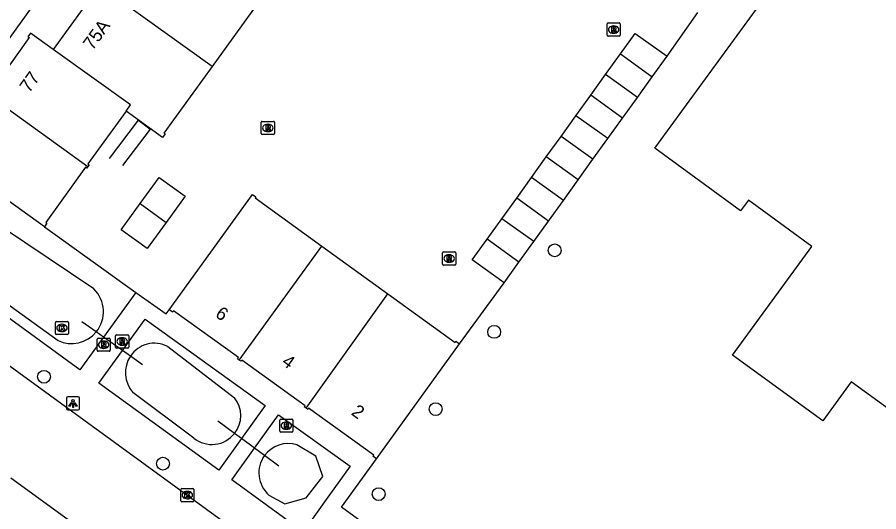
# Model space of a CAD drawing. Extents: x 159675 to 160530, y 382179 to 382901.
# Drawn here: x 160034.9 to 160100.6, y 382438.2 to 382475.9 of the extents above; entities that cross this region are included whole.
import ezdxf

# ---------------------------------------------------------------- set-up
doc = ezdxf.new("R2010")
doc.units = 0
for name, color, linetype in [('IMGEO_Boom', 7, 'Continuous'), ('IMGEO_Duiker', 7, 'Continuous'), ('IMGEO_Erf', 7, 'Continuous'), ('IMGEO_Groenvoorziening', 7, 'Continuous'), ('IMGEO_Hek', 7, 'Continuous'), ('IMGEO_Kolk', 7, 'Continuous'), ('IMGEO_Lichtpunt', 7, 'Continuous'), ('IMGEO_Pand', 7, 'Continuous'), ('IMGEO_Pand_nummerreeks', 7, 'Continuous'), ('IMGEO_Rijbaan_lokaal_open', 7, 'Continuous'), ('IMGEO_Rioolput', 7, 'Continuous'), ('IMGEO_Voetpad_open', 7, 'Continuous'), ('IMGEO_Waterloop', 7, 'Continuous')]:
    doc.layers.add(name, color=color, linetype=linetype)

msp = doc.modelspace()

# ---------------------------------------------------------------- linework, layer by layer
at = {"layer": 'IMGEO_Boom'}
for centre in [(160075.863, 382458.124), (160071.249, 382451.914), (160036.941, 382448.488), (160066.793, 382446.022), (160046.006, 382441.864), (160062.444, 382439.547)]:
    msp.add_circle(centre, 0.489, dxfattribs=at)
at = {"layer": 'IMGEO_Duiker'}
for points in [[(160044.452, 382449.408), (160043.529, 382450.059), (160042.922, 382450.487), (160041.474, 382451.508), (160040.915, 382451.903), (160039.813, 382452.68)], [(160054.834, 382441.676), (160053.747, 382442.479), (160052.977, 382443.048), (160051.982, 382443.784), (160051.461, 382444.169), (160050.195, 382445.105)]]:
    msp.add_lwpolyline(points, dxfattribs=at)
at = {"layer": 'IMGEO_Erf'}
for points in [[(160084.42, 382472.917), (160086.78, 382476.254)], [(160068.6, 382451.01), (160072.007, 382455.649)]]:
    msp.add_lwpolyline(points, dxfattribs=at)
at = {"layer": 'IMGEO_Groenvoorziening'}
msp.add_lwpolyline([(160036.972, 382459.928), (160043.937, 382454.91)], dxfattribs=at)
at = {"layer": 'IMGEO_Hek'}
msp.add_lwpolyline([(160041.939, 382465.12), (160044.148, 382468.038), (160045.027, 382467.372), (160042.916, 382464.583)], dxfattribs=at)
at = {"layer": 'IMGEO_Kolk'}
for p, q in [((160037.807, 382451.784), (160037.807, 382452.636)), ((160037.882, 382452.71), (160038.734, 382452.71)), ((160038.808, 382452.636), (160038.808, 382451.784)), ((160038.318, 382451.93), (160038.293, 382451.93)), ((160038.295, 382452.49), (160038.32, 382452.49)), ((160038.734, 382451.71), (160037.882, 382451.71)), ((160047.363, 382439.043), (160047.363, 382439.895)), ((160047.438, 382439.969), (160048.29, 382439.969)), ((160047.851, 382439.749), (160047.876, 382439.749)), ((160048.364, 382439.895), (160048.364, 382439.043)), ((160048.29, 382438.969), (160047.438, 382438.969)), ((160047.874, 382439.189), (160047.849, 382439.189))]:
    msp.add_line(p, q, dxfattribs=at)
for points in [[(160037.807, 382451.784), (160037.807, 382452.636)], [(160037.882, 382452.71), (160038.734, 382452.71)], [(160038.808, 382452.636), (160038.808, 382451.784)], [(160038.128, 382452.41), (160038.251, 382452.41), (160038.251, 382452.259), (160038.381, 382452.41), (160038.545, 382452.41), (160038.399, 382452.259), (160038.552, 382452.01), (160038.4, 382452.01), (160038.315, 382452.174), (160038.251, 382452.107), (160038.251, 382452.01), (160038.128, 382452.01), (160038.128, 382452.41)], [(160038.734, 382451.71), (160037.882, 382451.71)], [(160047.363, 382439.043), (160047.363, 382439.895)], [(160047.438, 382439.969), (160048.29, 382439.969)], [(160047.684, 382439.669), (160047.807, 382439.669), (160047.807, 382439.518), (160047.937, 382439.669), (160048.101, 382439.669), (160047.955, 382439.518), (160048.108, 382439.269), (160047.956, 382439.269), (160047.871, 382439.433), (160047.807, 382439.366), (160047.807, 382439.269), (160047.684, 382439.269), (160047.684, 382439.669)], [(160048.364, 382439.895), (160048.364, 382439.043)], [(160048.29, 382438.969), (160047.438, 382438.969)]]:
    msp.add_lwpolyline(points, dxfattribs=at)
for centre, start, end in [((160037.884, 382452.634), 91.55205, 178.44795), ((160037.884, 382452.634), 91.55205, 178.44795), ((160038.732, 382452.634), 1.55205, 88.44795), ((160038.732, 382452.634), 1.55205, 88.44795), ((160037.884, 382451.786), 181.55205, 268.44795), ((160037.884, 382451.786), 181.55205, 268.44795), ((160038.732, 382451.786), 271.55205, 358.44795), ((160038.732, 382451.786), 271.55205, 358.44795), ((160047.44, 382439.893), 91.55205, 178.44795), ((160047.44, 382439.893), 91.55205, 178.44795), ((160048.288, 382439.893), 1.55205, 88.44795), ((160048.288, 382439.893), 1.55205, 88.44795), ((160047.44, 382439.045), 181.55205, 268.44795), ((160047.44, 382439.045), 181.55205, 268.44795), ((160048.288, 382439.045), 271.55205, 358.44795), ((160048.288, 382439.045), 271.55205, 358.44795)]:
    msp.add_arc(centre, 0.0765, start, end, dxfattribs=at)
for centre, major_axis, ratio, start_param, end_param in [((160038.294, 382452.21), (-0.387, 0.002), 0.722429, 4.712389, 7.853982), ((160038.319, 382452.21), (-0.39, 0.002), 0.717154, 1.570796, 4.712389), ((160047.85, 382439.469), (-0.387, 0.002), 0.722429, 4.712389, 7.853982), ((160047.875, 382439.469), (-0.39, 0.002), 0.717154, 1.570796, 4.712389)]:
    msp.add_ellipse(centre, major_axis=major_axis, ratio=ratio, start_param=start_param, end_param=end_param, dxfattribs=at)
at = {"layer": 'IMGEO_Lichtpunt'}
for p, q in [((160038.654, 382446.861), (160038.654, 382446.054)), ((160038.654, 382446.861), (160038.654, 382446.054)), ((160039.556, 382446.956), (160038.748, 382446.956)), ((160039.556, 382446.956), (160038.748, 382446.956)), ((160039.65, 382446.054), (160039.65, 382446.861)), ((160039.65, 382446.054), (160039.65, 382446.861)), ((160038.748, 382445.96), (160039.556, 382445.96)), ((160038.748, 382445.96), (160039.556, 382445.96))]:
    msp.add_line(p, q, dxfattribs=at)
for points in [[(160039.028, 382446.525), (160039.067, 382446.497), (160038.879, 382446.235), (160038.841, 382446.262), (160039.028, 382446.525)], [(160039.13, 382446.477), (160039.177, 382446.477), (160039.177, 382446.155), (160039.13, 382446.155), (160039.13, 382446.477)], [(160039.24, 382446.497), (160039.278, 382446.524), (160039.465, 382446.262), (160039.426, 382446.234), (160039.24, 382446.497)]]:
    msp.add_lwpolyline(points, dxfattribs=at)
msp.add_circle((160039.153, 382446.659), 0.0994, dxfattribs=at)
for centre, start, end in [((160038.748, 382446.861), 90, 180), ((160038.748, 382446.861), 90, 180), ((160039.556, 382446.861), 0, 90), ((160039.556, 382446.861), 0, 90), ((160038.748, 382446.054), 180, 270), ((160038.748, 382446.054), 180, 270), ((160039.556, 382446.054), 270, 0), ((160039.556, 382446.054), 270, 360)]:
    msp.add_arc(centre, 0.0946, start, end, dxfattribs=at)
at = {"layer": 'IMGEO_Pand'}
for points in [[(160096.303, 382445.131), (160089.403, 382450.139), (160095.446, 382458.418), (160090.622, 382461.94), (160090.027, 382461.125), (160083.485, 382465.902), (160096.525, 382483.765), (160111.322, 382472.965)], [(160041.08, 382478.387), (160040.985, 382478.255), (160041.074, 382478.191), (160037.64, 382473.43)], [(160049.748, 382472.149), (160041.08, 382478.387)], [(160053.437, 382477.262), (160049.748, 382472.149)], [(160037.64, 382473.43), (160035.91, 382474.671), (160035.721, 382474.409), (160035.811, 382474.345), (160032.781, 382470.131), (160032.692, 382470.195), (160032.597, 382470.065)], [(160080.864, 382473.092), (160081.992, 382474.662), (160084.42, 382472.917)], [(160043.198, 382468.743), (160043.531, 382469.204), (160037.64, 382473.43)], [(160079.735, 382471.523), (160080.864, 382473.092)], [(160080.864, 382473.092), (160083.291, 382471.347)], [(160083.291, 382471.347), (160084.42, 382472.917)], [(160049.748, 382472.149), (160046.079, 382467.062), (160046.168, 382466.997), (160045.981, 382466.738), (160043.198, 382468.743)], [(160078.607, 382469.953), (160079.735, 382471.523)], [(160082.163, 382469.777), (160079.735, 382471.523)], [(160082.163, 382469.777), (160083.291, 382471.347)], [(160032.597, 382470.065), (160040.276, 382464.504)], [(160077.478, 382468.383), (160078.607, 382469.953)], [(160081.035, 382468.207), (160078.607, 382469.953)], [(160081.035, 382468.207), (160082.163, 382469.777)], [(160043.198, 382468.743), (160040.291, 382464.715), (160040.381, 382464.65), (160040.276, 382464.504)], [(160076.35, 382466.813), (160077.478, 382468.383)], [(160079.906, 382466.638), (160077.478, 382468.383)], [(160079.906, 382466.638), (160081.035, 382468.207)], [(160075.221, 382465.244), (160076.35, 382466.813)], [(160078.778, 382465.068), (160076.35, 382466.813)], [(160078.778, 382465.068), (160079.906, 382466.638)], [(160036.972, 382459.928), (160029.413, 382465.356)], [(160074.093, 382463.674), (160075.221, 382465.244)], [(160077.649, 382463.498), (160075.221, 382465.244)], [(160077.649, 382463.498), (160078.778, 382465.068)], [(160040.276, 382464.504), (160040.193, 382464.389), (160040.103, 382464.454), (160037.071, 382460.254), (160037.16, 382460.189), (160036.972, 382459.928)], [(160044.28, 382461.69), (160045.728, 382463.69), (160047.704, 382462.258), (160046.256, 382460.258)], [(160072.964, 382462.104), (160074.093, 382463.674)], [(160076.521, 382461.928), (160074.093, 382463.674)], [(160076.521, 382461.928), (160077.649, 382463.498)], [(160046.492, 382453.604), (160052.826, 382462.394), (160053.085, 382462.205), (160053.022, 382462.117), (160058.111, 382458.444)], [(160071.836, 382460.534), (160072.964, 382462.104)], [(160075.392, 382460.359), (160072.964, 382462.104)], [(160075.392, 382460.359), (160076.521, 382461.928)], [(160046.256, 382460.258), (160044.807, 382458.257), (160042.831, 382459.689), (160044.28, 382461.69)], [(160044.28, 382461.69), (160046.256, 382460.258)], [(160070.707, 382458.965), (160071.836, 382460.534)], [(160074.264, 382458.789), (160071.836, 382460.534)], [(160074.264, 382458.789), (160075.392, 382460.359)], [(160072.007, 382455.649), (160069.579, 382457.395), (160070.707, 382458.965)], [(160073.136, 382457.219), (160070.707, 382458.965)], [(160073.136, 382457.219), (160074.264, 382458.789)], [(160051.825, 382449.763), (160058.111, 382458.444)], [(160058.111, 382458.444), (160063.155, 382454.804)], [(160072.007, 382455.649), (160073.136, 382457.219)], [(160056.909, 382446.1), (160063.155, 382454.804)], [(160063.155, 382454.804), (160068.274, 382451.11), (160068.338, 382451.199), (160068.6, 382451.01)], [(160051.825, 382449.763), (160051.694, 382449.857), (160051.758, 382449.946), (160046.818, 382453.504), (160046.754, 382453.415), (160046.492, 382453.604)], [(160062.271, 382442.237), (160068.6, 382451.01)], [(160056.909, 382446.1), (160056.778, 382446.194), (160056.843, 382446.284), (160052.02, 382449.758), (160051.955, 382449.668), (160051.825, 382449.763)], [(160099.082, 382425.521), (160110.426, 382441.152), (160107.233, 382443.47), (160106.406, 382442.33), (160098.456, 382448.099), (160096.303, 382445.131)], [(160062.271, 382442.237), (160062.009, 382442.426), (160062.074, 382442.515), (160057.105, 382446.095), (160057.04, 382446.006), (160056.909, 382446.1)]]:
    msp.add_lwpolyline(points, dxfattribs=at)
at = {"layer": 'IMGEO_Rijbaan_lokaal_open'}
for points in [[(160018.366, 382460.946), (160123.455, 382384.426)], [(160099.29, 382393.592), (160034.415, 382440.769)]]:
    msp.add_lwpolyline(points, dxfattribs=at)
at = {"layer": 'IMGEO_Rioolput'}
for p, q in [((160079.858, 382474.527), (160079.858, 382475.379)), ((160079.933, 382475.453), (160080.785, 382475.453)), ((160080.346, 382475.233), (160080.371, 382475.233)), ((160080.859, 382475.379), (160080.859, 382474.527)), ((160080.785, 382474.453), (160079.933, 382474.453)), ((160080.369, 382474.673), (160080.344, 382474.673)), ((160053.503, 382467.031), (160053.503, 382467.883)), ((160053.578, 382467.957), (160054.43, 382467.957)), ((160053.991, 382467.737), (160054.016, 382467.737)), ((160054.504, 382467.883), (160054.504, 382467.031)), ((160054.014, 382467.177), (160053.989, 382467.177)), ((160054.43, 382466.957), (160053.578, 382466.957)), ((160067.315, 382457.078), (160067.315, 382457.93)), ((160067.39, 382458.004), (160068.242, 382458.004)), ((160068.316, 382457.93), (160068.316, 382457.078)), ((160067.826, 382457.224), (160067.801, 382457.224)), ((160067.803, 382457.784), (160067.828, 382457.784)), ((160068.242, 382457.004), (160067.39, 382457.004)), ((160040.988, 382450.506), (160040.988, 382451.358)), ((160041.063, 382451.432), (160041.915, 382451.432)), ((160041.989, 382451.358), (160041.989, 382450.506)), ((160042.394, 382450.753), (160042.394, 382451.605)), ((160042.469, 382451.679), (160043.321, 382451.679)), ((160042.882, 382451.459), (160042.907, 382451.459)), ((160043.395, 382451.605), (160043.395, 382450.753)), ((160041.499, 382450.652), (160041.474, 382450.652)), ((160041.476, 382451.212), (160041.501, 382451.212)), ((160043.321, 382450.679), (160042.469, 382450.679)), ((160042.905, 382450.899), (160042.88, 382450.899)), ((160041.915, 382450.432), (160041.063, 382450.432)), ((160054.913, 382444.341), (160054.913, 382445.193)), ((160054.988, 382445.267), (160055.84, 382445.267)), ((160055.401, 382445.047), (160055.426, 382445.047)), ((160055.914, 382445.193), (160055.914, 382444.341)), ((160055.84, 382444.267), (160054.988, 382444.267)), ((160055.424, 382444.487), (160055.399, 382444.487))]:
    msp.add_line(p, q, dxfattribs=at)
for points in [[(160079.858, 382474.527), (160079.858, 382475.379)], [(160079.933, 382475.453), (160080.785, 382475.453)], [(160080.447, 382475.151), (160080.195, 382475.153), (160080.195, 382474.753)], [(160080.195, 382474.753), (160080.319, 382474.753), (160080.319, 382474.915), (160080.33, 382474.915)], [(160080.373, 382475.072), (160080.319, 382475.072), (160080.319, 382474.991)], [(160080.319, 382474.991), (160080.371, 382474.991)], [(160080.859, 382475.379), (160080.859, 382474.527)], [(160080.785, 382474.453), (160079.933, 382474.453)], [(160080.377, 382474.886), (160080.448, 382474.753), (160080.588, 382474.753), (160080.523, 382474.879)], [(160053.503, 382467.031), (160053.503, 382467.883)], [(160053.578, 382467.957), (160054.43, 382467.957)], [(160054.504, 382467.883), (160054.504, 382467.031)], [(160054.092, 382467.655), (160053.84, 382467.657), (160053.84, 382467.257)], [(160053.84, 382467.257), (160053.964, 382467.257), (160053.964, 382467.419), (160053.975, 382467.419)], [(160054.018, 382467.576), (160053.964, 382467.576), (160053.964, 382467.495)], [(160053.964, 382467.495), (160054.016, 382467.495)], [(160054.022, 382467.39), (160054.093, 382467.257), (160054.233, 382467.257), (160054.168, 382467.383)], [(160054.43, 382466.957), (160053.578, 382466.957)], [(160067.315, 382457.078), (160067.315, 382457.93)], [(160067.39, 382458.004), (160068.242, 382458.004)], [(160068.316, 382457.93), (160068.316, 382457.078)], [(160067.904, 382457.702), (160067.652, 382457.704), (160067.652, 382457.304)], [(160067.652, 382457.304), (160067.776, 382457.304), (160067.776, 382457.466), (160067.787, 382457.466)], [(160067.83, 382457.623), (160067.776, 382457.623), (160067.776, 382457.542)], [(160067.776, 382457.542), (160067.828, 382457.542)], [(160067.834, 382457.437), (160067.905, 382457.304), (160068.045, 382457.304), (160067.98, 382457.43)], [(160068.242, 382457.004), (160067.39, 382457.004)], [(160040.988, 382450.506), (160040.988, 382451.358)], [(160041.063, 382451.432), (160041.915, 382451.432)], [(160041.989, 382451.358), (160041.989, 382450.506)], [(160042.394, 382450.753), (160042.394, 382451.605)], [(160042.469, 382451.679), (160043.321, 382451.679)], [(160042.983, 382451.377), (160042.731, 382451.379), (160042.731, 382450.979)], [(160042.909, 382451.298), (160042.855, 382451.298), (160042.855, 382451.217)], [(160043.395, 382451.605), (160043.395, 382450.753)], [(160041.577, 382451.13), (160041.325, 382451.132), (160041.325, 382450.732)], [(160041.325, 382450.732), (160041.449, 382450.732), (160041.449, 382450.894), (160041.46, 382450.894)], [(160041.503, 382451.051), (160041.449, 382451.051), (160041.449, 382450.97)], [(160041.449, 382450.97), (160041.501, 382450.97)], [(160041.507, 382450.865), (160041.578, 382450.732), (160041.718, 382450.732), (160041.653, 382450.858)], [(160043.321, 382450.679), (160042.469, 382450.679)], [(160042.731, 382450.979), (160042.855, 382450.979), (160042.855, 382451.141), (160042.866, 382451.141)], [(160042.855, 382451.217), (160042.907, 382451.217)], [(160042.913, 382451.112), (160042.984, 382450.979), (160043.124, 382450.979), (160043.059, 382451.105)], [(160041.915, 382450.432), (160041.063, 382450.432)], [(160054.913, 382444.341), (160054.913, 382445.193)], [(160054.988, 382445.267), (160055.84, 382445.267)], [(160055.502, 382444.965), (160055.25, 382444.967), (160055.25, 382444.567)], [(160055.25, 382444.567), (160055.374, 382444.567), (160055.374, 382444.729), (160055.385, 382444.729)], [(160055.428, 382444.886), (160055.374, 382444.886), (160055.374, 382444.805)], [(160055.374, 382444.805), (160055.426, 382444.805)], [(160055.914, 382445.193), (160055.914, 382444.341)], [(160055.84, 382444.267), (160054.988, 382444.267)], [(160055.432, 382444.7), (160055.503, 382444.567), (160055.643, 382444.567), (160055.578, 382444.693)]]:
    msp.add_lwpolyline(points, dxfattribs=at)
for centre, radius, start, end in [((160079.935, 382475.377), 0.0765, 91.55205, 178.44795), ((160079.935, 382475.377), 0.0765, 91.55205, 178.44795), ((160080.329, 382474.862), 0.0533, 26.02933, 88.69889), ((160080.355, 382475.18), 0.19, 274.7715, 282.96867), ((160080.379, 382474.976), 0.0964, 77.00612, 93.18647), ((160080.393, 382475.033), 0.0378, 276.66336, 79.67722), ((160080.446, 382475.041), 0.109, 350.36119, 89.41601), ((160080.444, 382475.041), 0.112, 277.58423, 350.98172), ((160080.428, 382474.826), 0.108, 29.51342, 73.79051), ((160080.783, 382475.377), 0.0765, 1.55205, 88.44795), ((160080.783, 382475.377), 0.0765, 1.55205, 88.44795), ((160079.935, 382474.529), 0.0765, 181.55205, 268.44795), ((160079.935, 382474.529), 0.0765, 181.55205, 268.44795), ((160080.783, 382474.529), 0.0765, 271.55205, 358.44795), ((160080.783, 382474.529), 0.0765, 271.55205, 358.44795), ((160053.58, 382467.881), 0.0765, 91.55205, 178.44795), ((160053.58, 382467.881), 0.0765, 91.55205, 178.44795), ((160054.428, 382467.881), 0.0765, 1.55205, 88.44795), ((160054.428, 382467.881), 0.0765, 1.55205, 88.44795), ((160053.58, 382467.033), 0.0765, 181.55205, 268.44795), ((160053.58, 382467.033), 0.0765, 181.55205, 268.44795), ((160053.974, 382467.366), 0.0533, 26.02933, 88.69889), ((160054, 382467.684), 0.19, 274.7715, 282.96867), ((160054.024, 382467.48), 0.0964, 77.00612, 93.18647), ((160054.038, 382467.537), 0.0378, 276.66336, 79.67722), ((160054.091, 382467.545), 0.109, 350.36119, 89.41601), ((160054.089, 382467.545), 0.112, 277.58423, 350.98172), ((160054.073, 382467.33), 0.108, 29.51342, 73.79051), ((160054.428, 382467.033), 0.0765, 271.55205, 358.44795), ((160054.428, 382467.033), 0.0765, 271.55205, 358.44795), ((160067.392, 382457.928), 0.0765, 91.55205, 178.44795), ((160067.392, 382457.928), 0.0765, 91.55205, 178.44795), ((160068.24, 382457.928), 0.0765, 1.55205, 88.44795), ((160068.24, 382457.928), 0.0765, 1.55205, 88.44795), ((160067.786, 382457.413), 0.0533, 26.02933, 88.69889), ((160067.812, 382457.731), 0.19, 274.7715, 282.96867), ((160067.836, 382457.527), 0.0964, 77.00612, 93.18647), ((160067.85, 382457.584), 0.0378, 276.66336, 79.67722), ((160067.903, 382457.592), 0.109, 350.36119, 89.41601), ((160067.901, 382457.592), 0.112, 277.58423, 350.98172), ((160067.885, 382457.377), 0.108, 29.51342, 73.79051), ((160067.392, 382457.08), 0.0765, 181.55205, 268.44795), ((160067.392, 382457.08), 0.0765, 181.55205, 268.44795), ((160068.24, 382457.08), 0.0765, 271.55205, 358.44795), ((160068.24, 382457.08), 0.0765, 271.55205, 358.44795), ((160041.065, 382451.356), 0.0765, 91.55205, 178.44795), ((160041.065, 382451.356), 0.0765, 91.55205, 178.44795), ((160041.913, 382451.356), 0.0765, 1.55205, 88.44795), ((160041.913, 382451.356), 0.0765, 1.55205, 88.44795), ((160042.471, 382451.603), 0.0765, 91.55205, 178.44795), ((160042.471, 382451.603), 0.0765, 91.55205, 178.44795), ((160042.915, 382451.202), 0.0964, 77.00612, 93.18647), ((160042.929, 382451.259), 0.0378, 276.66336, 79.67722), ((160042.982, 382451.267), 0.109, 350.36119, 89.41601), ((160043.319, 382451.603), 0.0765, 1.55205, 88.44795), ((160043.319, 382451.603), 0.0765, 1.55205, 88.44795), ((160041.459, 382450.841), 0.0533, 26.02933, 88.69889), ((160041.485, 382451.159), 0.19, 274.7715, 282.96867), ((160041.509, 382450.955), 0.0964, 77.00612, 93.18647), ((160041.523, 382451.012), 0.0378, 276.66336, 79.67722), ((160041.576, 382451.02), 0.109, 350.36119, 89.41601), ((160041.574, 382451.02), 0.112, 277.58423, 350.98172), ((160041.558, 382450.805), 0.108, 29.51342, 73.79051), ((160042.471, 382450.755), 0.0765, 181.55205, 268.44795), ((160042.471, 382450.755), 0.0765, 181.55205, 268.44795), ((160042.865, 382451.088), 0.0533, 26.02933, 88.69889), ((160042.891, 382451.406), 0.19, 274.7715, 282.96867), ((160042.98, 382451.267), 0.112, 277.58423, 350.98172), ((160042.964, 382451.052), 0.108, 29.51342, 73.79051), ((160043.319, 382450.755), 0.0765, 271.55205, 358.44795), ((160043.319, 382450.755), 0.0765, 271.55205, 358.44795), ((160041.065, 382450.508), 0.0765, 181.55205, 268.44795), ((160041.065, 382450.508), 0.0765, 181.55205, 268.44795), ((160041.913, 382450.508), 0.0765, 271.55205, 358.44795), ((160041.913, 382450.508), 0.0765, 271.55205, 358.44795), ((160054.99, 382445.191), 0.0765, 91.55205, 178.44795), ((160054.99, 382445.191), 0.0765, 91.55205, 178.44795), ((160055.384, 382444.676), 0.0533, 26.02933, 88.69889), ((160055.41, 382444.994), 0.19, 274.7715, 282.96867), ((160055.434, 382444.79), 0.0964, 77.00612, 93.18647), ((160055.448, 382444.847), 0.0378, 276.66336, 79.67722), ((160055.501, 382444.855), 0.109, 350.36119, 89.41601), ((160055.499, 382444.855), 0.112, 277.58423, 350.98172), ((160055.483, 382444.64), 0.108, 29.51342, 73.79051), ((160055.838, 382445.191), 0.0765, 1.55205, 88.44795), ((160055.838, 382445.191), 0.0765, 1.55205, 88.44795), ((160054.99, 382444.343), 0.0765, 181.55205, 268.44795), ((160054.99, 382444.343), 0.0765, 181.55205, 268.44795), ((160055.838, 382444.343), 0.0765, 271.55205, 358.44795), ((160055.838, 382444.343), 0.0765, 271.55205, 358.44795)]:
    msp.add_arc(centre, radius, start, end, dxfattribs=at)
for centre, major_axis, ratio, start_param, end_param in [((160080.345, 382474.953), (-0.387, 0.002), 0.722429, 4.712389, 7.853982), ((160080.37, 382474.953), (-0.39, 0.002), 0.717154, 1.570796, 4.712389), ((160053.99, 382467.457), (-0.387, 0.002), 0.722429, 4.712389, 7.853982), ((160054.015, 382467.457), (-0.39, 0.002), 0.717154, 1.570796, 4.712389), ((160067.802, 382457.504), (-0.387, 0.002), 0.722429, 4.712389, 7.853982), ((160067.827, 382457.504), (-0.39, 0.002), 0.717154, 1.570796, 4.712389), ((160042.881, 382451.179), (-0.387, 0.002), 0.722429, 4.712389, 7.853982), ((160042.906, 382451.179), (-0.39, 0.002), 0.717154, 1.570796, 4.712389), ((160041.475, 382450.932), (-0.387, 0.002), 0.722429, 4.712389, 7.853982), ((160041.5, 382450.932), (-0.39, 0.002), 0.717154, 1.570796, 4.712389), ((160055.4, 382444.767), (-0.387, 0.002), 0.722429, 4.712389, 7.853982), ((160055.425, 382444.767), (-0.39, 0.002), 0.717154, 1.570796, 4.712389)]:
    msp.add_ellipse(centre, major_axis=major_axis, ratio=ratio, start_param=start_param, end_param=end_param, dxfattribs=at)
at = {"layer": 'IMGEO_Voetpad_open'}
for points in [[(160024.222, 382460.289), (160027.135, 382464.334), (160037.642, 382478.923), (160031.503, 382483.33), (160023.13, 382471.823), (160022.611, 382472.173), (160019.765, 382468.28), (160020.141, 382468.006), (160019.056, 382466.519), (160018.758, 382466.11)], [(160043.937, 382454.91), (160041.474, 382451.508), (160039.671, 382449.018), (160025.191, 382459.567)], [(160043.937, 382454.91), (160046.246, 382453.281), (160046.492, 382453.604)], [(160051.982, 382443.784), (160050.253, 382441.367), (160041.115, 382447.994), (160042.922, 382450.487), (160044.658, 382452.884), (160053.788, 382446.31), (160051.982, 382443.784)], [(160058.575, 382439.306), (160056.683, 382436.674), (160051.245, 382440.646), (160052.977, 382443.048), (160054.806, 382445.584), (160060.282, 382441.681), (160058.575, 382439.306)], [(160125.462, 382390.566), (160059.604, 382438.555), (160062.271, 382442.237)]]:
    msp.add_lwpolyline(points, dxfattribs=at)
at = {"layer": 'IMGEO_Waterloop'}
for points in [[(160040.732, 382455.196), (160030.284, 382462.211)], [(160027.312, 382458.967), (160038.018, 382451.248)], [(160046.37, 382450.793), (160051.466, 382446.887)], [(160048.362, 382443.814), (160043.723, 382447.303)], [(160058.184, 382440.877), (160057.65, 382442.427), (160056.213, 382443.302)], [(160054.078, 382439.477), (160055.284, 382438.815), (160056.933, 382439.263), (160058.184, 382440.877)]]:
    msp.add_lwpolyline(points, dxfattribs=at)
for centre, radius, start, end in [((160039.043, 382453.451), 2.429, 320.42749, 45.9341), ((160039.043, 382453.446), 2.426, 244.99231, 320.48797), ((160045.345, 382448.896), 2.156, 61.60852, 147.36379), ((160045.369, 382448.804), 2.227, 145.68961, 222.36342), ((160049.745, 382445.531), 2.191, 321.56384, 38.22535), ((160049.735, 382445.528), 2.197, 231.2991, 321.77074), ((160055.558, 382441.16), 2.24, 72.98827, 143.92344), ((160055.557, 382441.159), 2.24, 143.90673, 228.67728)]:
    msp.add_arc(centre, radius, start, end, dxfattribs=at)

# ---------------------------------------------------------------- texts
at = {"layer": 'IMGEO_Pand_nummerreeks'}
for s, rotation, p in [('75A', 54.19608, (160040.642, 382473.318)), ('77', 54.28202, (160035.816, 382470.071)), ('6', 324.23597, (160049.922, 382453.117)), ('4', 324.23597, (160054.992, 382449.466)), ('2', 324.23024, (160060.292, 382445.647))]:
    msp.add_text(s, height=1, rotation=rotation, dxfattribs=at).set_placement(p)

doc.saveas('drawing.dxf')
